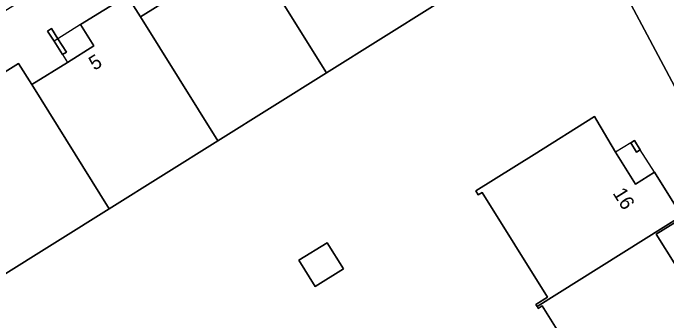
# Model space of a CAD drawing. Extents: x 158835 to 160077, y 386387 to 387778.
# Drawn here: x 159146.99 to 159192.87, y 387136.96 to 387158.57 of the extents above; entities that cross this region are included whole.
import ezdxf

# ---------------------------------------------------------------- set-up
doc = ezdxf.new("R2010")
doc.units = 0
for name, color, linetype in [('IMGEO_Erf', 7, 'Continuous'), ('IMGEO_Muur', 7, 'Continuous'), ('IMGEO_Pand', 7, 'Continuous'), ('IMGEO_Pand_nummerreeks', 7, 'Continuous'), ('IMGEO_Pand_overbouw', 7, 'Continuous'), ('IMGEO_Voetpad_open', 7, 'Continuous')]:
    doc.layers.add(name, color=color, linetype=linetype)

msp = doc.modelspace()

# ---------------------------------------------------------------- linework, layer by layer
at = {"layer": 'IMGEO_Erf'}
for points in [[(159192.812, 387154.528), (159184.858, 387169.495), (159180.565, 387177.574), (159180.465, 387177.724), (159180.352, 387177.865), (159180.227, 387177.995), (159180.091, 387178.113), (159179.944, 387178.219), (159179.789, 387178.311), (159179.627, 387178.389), (159179.458, 387178.452), (159179.284, 387178.5), (159179.106, 387178.532), (159178.926, 387178.548), (159178.746, 387178.548), (159178.566, 387178.532), (159178.388, 387178.5), (159178.214, 387178.452), (159178.045, 387178.389), (159177.883, 387178.311), (159177.794, 387178.26), (159131.832, 387149.649)], [(159144.089, 387152.989), (159147.369, 387155.042), (159148.301, 387153.547), (159150.796, 387155.109), (159152.651, 387156.271), (159151.717, 387157.762), (159154.991, 387159.812), (159155.923, 387158.318), (159158.418, 387159.88)], [(159176.61, 387159.141), (159168.985, 387154.372), (159161.359, 387149.602), (159153.734, 387144.832), (159146.108, 387140.062)], [(159261.184, 387025.643), (159192.812, 387154.528)], [(159185.526, 387135.77), (159184.124, 387138.013), (159183.844, 387137.839), (159183.759, 387137.975), (159183.675, 387138.11), (159184.497, 387138.624), (159179.898, 387145.985), (159179.619, 387145.81), (159179.449, 387146.081), (159183.548, 387148.651), (159187.784, 387151.306), (159187.952, 387151.035), (159189.27, 387148.801), (159190.657, 387146.562), (159191.987, 387147.393), (159193.819, 387144.47)], [(159194.268, 387144.374), (159192.122, 387143.048), (159193.485, 387140.842)]]:
    msp.add_lwpolyline(points, dxfattribs=at)
for points in [[(159150.454, 387155.656), (159149.862, 387156.601), (159149.403, 387157.31), (159149.675, 387157.483), (159150.124, 387156.765), (159150.725, 387155.825)], [(159190.328, 387149.458), (159190.591, 387149.622), (159191, 387148.969), (159190.737, 387148.805)], [(159168.19, 387139.384), (159167.046, 387141.214), (159169.026, 387142.451), (159170.169, 387140.621)]]:
    msp.add_lwpolyline(points, close=True, dxfattribs=at)
at = {"layer": 'IMGEO_Muur'}
msp.add_lwpolyline([(159184.858, 387169.495), (159192.812, 387154.528)], dxfattribs=at)
at = {"layer": 'IMGEO_Pand'}
for points in [[(159171.188, 387167.875), (159170.261, 387169.369), (159166.968, 387167.308), (159167.902, 387165.816), (159166.048, 387164.656), (159163.545, 387163.089), (159168.985, 387154.372), (159176.61, 387159.141)], [(159163.545, 387163.089), (159162.613, 387164.583), (159159.338, 387162.533), (159160.272, 387161.041), (159158.418, 387159.88), (159155.923, 387158.318), (159161.359, 387149.602), (159168.985, 387154.372)], [(159155.923, 387158.318), (159154.991, 387159.812), (159151.717, 387157.762), (159152.651, 387156.271), (159150.796, 387155.109), (159148.301, 387153.547), (159153.734, 387144.832), (159161.359, 387149.602)], [(159150.124, 387156.765), (159149.675, 387157.483), (159149.403, 387157.31), (159149.862, 387156.601), (159150.454, 387155.656), (159150.725, 387155.825)], [(159148.301, 387153.547), (159147.369, 387155.042), (159144.089, 387152.989), (159145.023, 387151.496), (159143.174, 387150.339), (159140.678, 387148.777), (159146.108, 387140.062), (159153.734, 387144.832)], [(159191.987, 387147.393), (159190.657, 387146.562), (159189.27, 387148.801), (159187.952, 387151.035), (159187.784, 387151.306), (159183.548, 387148.651), (159179.449, 387146.081), (159179.619, 387145.81), (159179.898, 387145.985), (159184.497, 387138.624), (159183.675, 387138.11), (159183.759, 387137.975), (159194.183, 387144.51), (159194.098, 387144.645), (159193.819, 387144.47)], [(159190.591, 387149.622), (159190.328, 387149.458), (159190.737, 387148.805), (159191, 387148.969)], [(159196.207, 387139.421), (159194.877, 387138.59), (159193.485, 387140.842), (159192.122, 387143.048), (159194.268, 387144.374), (159194.183, 387144.51), (159183.759, 387137.975), (159183.844, 387137.839), (159184.124, 387138.013), (159185.526, 387135.77), (159182.473, 387133.859), (159185.676, 387128.741), (159187.901, 387130.139), (159187.985, 387130.004), (159198.406, 387136.526), (159198.321, 387136.662), (159198.041, 387136.487)], [(159167.046, 387141.214), (159168.19, 387139.384), (159170.169, 387140.621), (159169.026, 387142.451)]]:
    msp.add_lwpolyline(points, close=True, dxfattribs=at)
at = {"layer": 'IMGEO_Pand_overbouw'}
for points in [[(159150.124, 387156.765), (159149.862, 387156.601), (159150.454, 387155.656), (159150.796, 387155.109), (159152.651, 387156.271), (159151.717, 387157.762)], [(159191, 387148.969), (159190.591, 387149.622), (159190.328, 387149.458), (159189.27, 387148.801), (159190.657, 387146.562), (159191.987, 387147.393)]]:
    msp.add_lwpolyline(points, close=True, dxfattribs=at)
at = {"layer": 'IMGEO_Voetpad_open'}
msp.add_lwpolyline([(159184.858, 387169.495), (159192.812, 387154.528), (159261.184, 387025.643)], dxfattribs=at)

# ---------------------------------------------------------------- texts
at = {"layer": 'IMGEO_Pand_nummerreeks'}
for s, rotation, p in [('5', 32.0398, (159152.697, 387154.506)), ('16', 302.0682, (159189.036, 387145.927))]:
    msp.add_text(s, height=1, rotation=rotation, dxfattribs=at).set_placement(p)

doc.saveas('drawing.dxf')
